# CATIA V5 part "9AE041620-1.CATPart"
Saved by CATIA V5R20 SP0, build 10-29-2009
Part number: 9AE041620-1
Revision: ANY
Definition: UNKNOWN
Nomenclature: 9AE041620-1
Source: Unknown
Bounding box of the stored display mesh (mm): x -9.45 to 3.05, y -22 to 27, z -6.093 to 6.093
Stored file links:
  C:\Users\Utente\Desktop\IO LAVORO\3D X SITO CF\CUMSA\3D files AE\AE 041620\9AE041620-1.CATPart
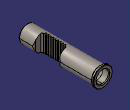
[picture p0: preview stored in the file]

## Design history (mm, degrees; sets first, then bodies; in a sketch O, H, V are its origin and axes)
Body1 "Chaflán1" (main body)
  Solid1: solid without history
